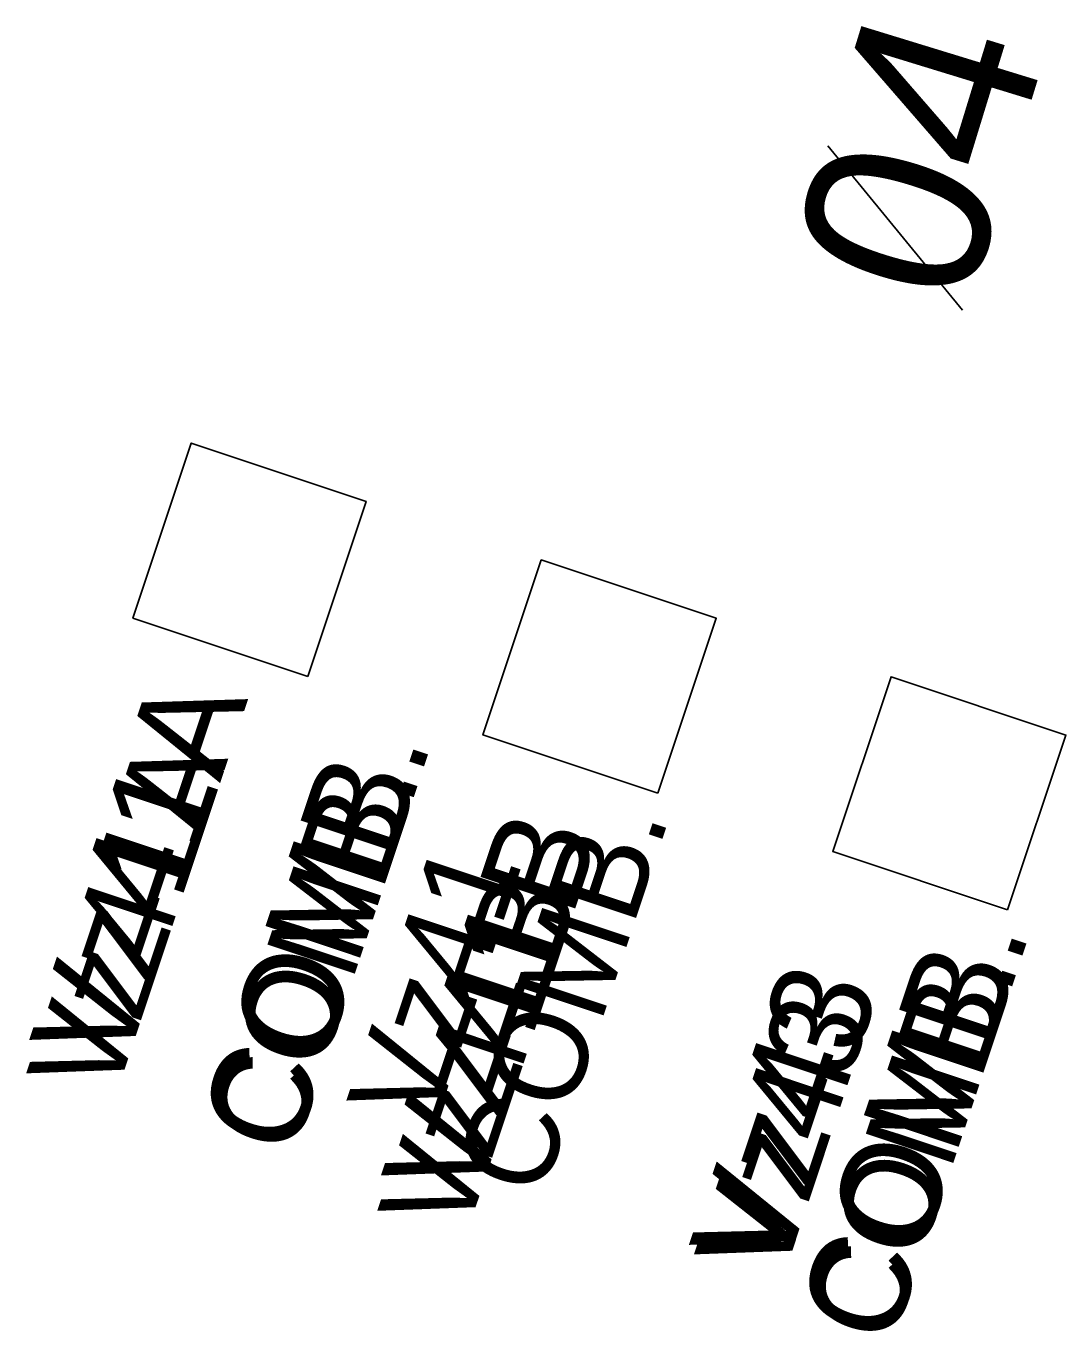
# Model space of a CAD drawing. Extents: x 647787 to 668496, y 640478 to 654412.
# Drawn here: x 662704.21 to 662738.05, y 647107.32 to 647149.81 of the extents above; entities that cross this region are included whole.
import ezdxf

# ---------------------------------------------------------------- set-up
doc = ezdxf.new("R2010")
doc.units = 0
for name, color, linetype in [('Default', 7, 'Continuous'), ('TEMP_DETECTION ZONE_Stage 2', 7, 'Continuous'), ('TEMP_DETECTION ZONE_STAGE 3', 7, 'Continuous'), ('TEMP_DETECTION_ZONE_STAGE 4', 7, 'Continuous'), ('TEMP_DETECTION_ZONE_STAGE 5', 7, 'Continuous'), ('TEMP_SIGNAL_POLES_STAGE 1B', 7, 'Continuous')]:
    doc.layers.add(name, color=color, linetype=linetype)

msp = doc.modelspace()

# ---------------------------------------------------------------- linework, layer by layer
at = {"layer": 'Default'}
msp.add_line((662730.304, 647145.907), (662734.687, 647140.563), dxfattribs=at)
msp.add_line((662730.304, 647145.907), (662734.687, 647140.563), dxfattribs=at)
msp.add_line((662730.304, 647145.907), (662734.687, 647140.563), dxfattribs=at)
msp.add_line((662730.304, 647145.907), (662734.687, 647140.563), dxfattribs=at)
msp.add_line((662730.304, 647145.907), (662734.687, 647140.563), dxfattribs=at)
msp.add_line((662730.304, 647145.907), (662734.687, 647140.563), dxfattribs=at)
at = {"layer": 'TEMP_DETECTION ZONE_Stage 2'}
for points in [[(662724.769, 647124.847), (662719.078, 647126.746), (662720.977, 647132.438), (662726.669, 647130.538)], [(662736.152, 647121.048), (662730.461, 647122.947), (662732.36, 647128.639), (662738.052, 647126.74)]]:
    msp.add_lwpolyline(points, close=True, dxfattribs=at)
at = {"layer": 'TEMP_DETECTION ZONE_STAGE 3'}
for points in [[(662713.378, 647128.648), (662707.687, 647130.548), (662709.586, 647136.239), (662715.277, 647134.34)], [(662724.769, 647124.847), (662719.078, 647126.746), (662720.977, 647132.438), (662726.669, 647130.538)], [(662736.152, 647121.048), (662730.461, 647122.947), (662732.36, 647128.639), (662738.052, 647126.74)]]:
    msp.add_lwpolyline(points, close=True, dxfattribs=at)
at = {"layer": 'TEMP_DETECTION_ZONE_STAGE 4'}
for points in [[(662713.378, 647128.648), (662707.687, 647130.548), (662709.586, 647136.239), (662715.277, 647134.34)], [(662724.769, 647124.847), (662719.078, 647126.746), (662720.977, 647132.438), (662726.669, 647130.538)], [(662736.152, 647121.048), (662730.461, 647122.947), (662732.36, 647128.639), (662738.052, 647126.74)]]:
    msp.add_lwpolyline(points, close=True, dxfattribs=at)
at = {"layer": 'TEMP_DETECTION_ZONE_STAGE 5'}
for points in [[(662713.378, 647128.648), (662707.687, 647130.548), (662709.586, 647136.239), (662715.277, 647134.34)], [(662724.769, 647124.847), (662719.078, 647126.746), (662720.977, 647132.438), (662726.669, 647130.538)], [(662736.152, 647121.048), (662730.461, 647122.947), (662732.36, 647128.639), (662738.052, 647126.74)]]:
    msp.add_lwpolyline(points, close=True, dxfattribs=at)
at = {"layer": 'TEMP_SIGNAL_POLES_STAGE 1B'}
for points in [[(662713.378, 647128.648), (662707.687, 647130.548), (662709.586, 647136.239), (662715.277, 647134.34)], [(662724.769, 647124.847), (662719.078, 647126.746), (662720.977, 647132.438), (662726.669, 647130.538)], [(662736.152, 647121.048), (662730.461, 647122.947), (662732.36, 647128.639), (662738.052, 647126.74)]]:
    msp.add_lwpolyline(points, close=True, dxfattribs=at)

# ---------------------------------------------------------------- texts
at = {"layer": 'Default'}
msp.add_text('04', height=6, rotation=72.9531, dxfattribs=at).set_placement((662734.811, 647140.483))
msp.add_text('04', height=6, rotation=72.9531, dxfattribs=at).set_placement((662734.811, 647140.483))
msp.add_text('04', height=6, rotation=72.9531, dxfattribs=at).set_placement((662734.811, 647140.483))
msp.add_text('04', height=6, rotation=72.9531, dxfattribs=at).set_placement((662734.811, 647140.483))
msp.add_text('04', height=6, rotation=72.9531, dxfattribs=at).set_placement((662734.811, 647140.483))
msp.add_text('04', height=6, rotation=72.9531, dxfattribs=at).set_placement((662734.811, 647140.483))
at = {"layer": 'TEMP_DETECTION ZONE_Stage 2'}
for s, p in [('COMB.', (662720.994, 647111.597)), ('Vz41', (662717.471, 647113.88)), ('COMB.', (662732.378, 647106.798)), ('Vz43', (662728.786, 647108.874))]:
    msp.add_text(s, height=3, rotation=71.5452, dxfattribs=at).set_placement(p)
at = {"layer": 'TEMP_DETECTION ZONE_STAGE 3'}
for s, p in [('Vz41A', (662707.049, 647114.765)), ('COMB.', (662712.9, 647112.953)), ('Vz41B', (662718.477, 647110.292)), ('COMB.', (662732.378, 647106.798)), ('Vz43', (662728.786, 647108.874))]:
    msp.add_text(s, height=3, rotation=71.5452, dxfattribs=at).set_placement(p)
at = {"layer": 'TEMP_DETECTION_ZONE_STAGE 4'}
for s, p in [('Vz41A', (662707.049, 647114.765)), ('COMB.', (662712.9, 647112.953)), ('Vz41B', (662718.477, 647110.292)), ('COMB.', (662732.378, 647106.798)), ('Vz43', (662728.786, 647108.874))]:
    msp.add_text(s, height=3, rotation=71.5452, dxfattribs=at).set_placement(p)
at = {"layer": 'TEMP_DETECTION_ZONE_STAGE 5'}
for s, p in [('Vz41A', (662707.049, 647114.765)), ('COMB.', (662712.9, 647112.953)), ('Vz41B', (662718.477, 647110.292)), ('COMB.', (662732.378, 647106.798)), ('Vz43', (662728.786, 647108.874))]:
    msp.add_text(s, height=3, rotation=71.5452, dxfattribs=at).set_placement(p)
at = {"layer": 'TEMP_SIGNAL_POLES_STAGE 1B'}
for s, p in [('Vz41A', (662707.385, 647115.772)), ('COMB.', (662712.907, 647112.975)), ('Vz41B', (662718.834, 647111.362)), ('COMB.', (662732.385, 647106.82)), ('Vz43', (662728.857, 647109.103))]:
    msp.add_text(s, height=3.25, rotation=71.5452, dxfattribs=at).set_placement(p)

doc.saveas('drawing.dxf')
